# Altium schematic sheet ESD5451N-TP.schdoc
size 127 x 101 mm
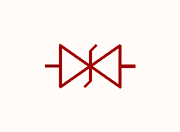
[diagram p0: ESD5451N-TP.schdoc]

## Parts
D?  esd5451n-tp  [D0402-BI]  (value not drawn)

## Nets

Not connected (* = marked no-connect by the designer): D? 1(K) 2(A)

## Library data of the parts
D? = esd5451n-tp: 极性:双向;反向截止电压(Vrwm):5V;钳位电压:11V;峰值脉冲电流(Ipp):7A@8/20us;峰值脉冲功率(Ppp):72W@8/20us;击穿电压:8.4V;; Manufacturer: TECH PUBLIC(台舟); AddInBom: yes; ModelId: 62a80a189f1b46df8ba79817b730b378; ModelName: D0402_L1.0-W0.5-H0.5; ModelTransform: 39.37,19.685,0,0,0,0,0,0,0; Polarity: 双向; Reverse Stand-Off Voltage (Vrwm): 5V; Clamping Voltage: 11V; Voltage - Breakdown: 8.4V; Reverse Leakage Current (Ir): 80nA; Number of Channels: 单路; level of protection: IEC 61000-4-2；IEC 61000-4-5; Type: ESD; Junction Capacitance: 12pF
